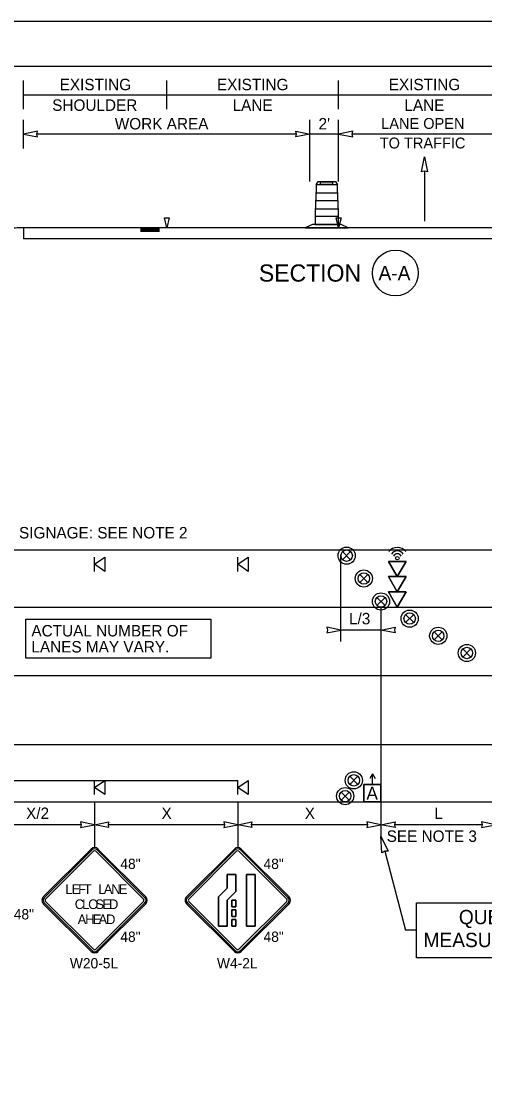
# Model space of a CAD drawing. Extents: x 99999 to 100116, y 99995 to 100013.
# Drawn here: x 100024.26 to 100027.5, y 100003.19 to 100010.69 of the extents above; entities that cross this region are included whole.
import ezdxf

# ---------------------------------------------------------------- set-up
doc = ezdxf.new("R2010")
doc.units = 0
for name, color, linetype in [('RD_ED_ShoulderPavedEdge', 7, 'Continuous'), ('RD_MK_LineEdgeWhite', 7, 'Continuous'), ('RD_MK_LineEdgeYellow', 7, 'Continuous'), ('RD_MK_LineLane', 7, 'Continuous'), ('SH_GI_PlotLimits', 7, 'Continuous'), ('SH_GI_SheetBorder', 7, 'Continuous'), ('SH_TI_Tables', 7, 'Continuous'), ('SH_TI_WZSectionCut', 7, 'Continuous'), ('TR_SN_ConstructionSigns', 7, 'Continuous'), ('TR_WZ_ArrowLeftStrRightTurn', 7, 'Continuous'), ('TR_WZ_PortableSignMountBlk-Org', 7, 'Continuous'), ('TR_WZ_SequentialArrowSign', 7, 'Continuous'), ('TR_WZ_TrafficSafetyDrum', 7, 'Continuous'), ('TR_WZ_TrafficSafetyDrumElev', 7, 'Continuous'), ('TR_WZ_WorkZoneDetails', 7, 'Continuous'), ('TR_WZ_WorkZoneTextCurrent', 7, 'Continuous')]:
    doc.layers.add(name, color=color, linetype=linetype)

msp = doc.modelspace()

# ---------------------------------------------------------------- linework, layer by layer
at = {"layer": 'RD_ED_ShoulderPavedEdge'}
for p, q in [((100021.7753, 100006.9957), (100035.62, 100006.9957)), ((100021.7753, 100005.2357), (100035.62, 100005.2357))]:
    msp.add_line(p, q, dxfattribs=at)
at = {"layer": 'RD_MK_LineEdgeWhite'}
msp.add_line((100021.7753, 100005.6357), (100035.62, 100005.6357), dxfattribs=at)
at = {"layer": 'RD_MK_LineEdgeYellow'}
msp.add_line((100021.7753, 100006.5957), (100035.62, 100006.5957), dxfattribs=at)
at = {"layer": 'RD_MK_LineLane'}
msp.add_lwpolyline([(100035.62, 100006.1157), (100021.7753, 100006.1157)], dxfattribs=at)
at = {"layer": 'SH_GI_PlotLimits'}
msp.add_lwpolyline([(100019.0625, 99999.6875), (100036.0625, 99999.6875), (100036.0625, 100010.6875), (100019.0625, 100010.6875)], close=True, dxfattribs=at)
at = {"layer": 'SH_GI_SheetBorder'}
msp.add_line((100020, 100010.375), (100035.75, 100010.375), dxfattribs=at)
at = {"layer": 'SH_TI_Tables'}
msp.add_lwpolyline([(100024.2941, 100006.511), (100025.5872, 100006.511), (100025.5872, 100006.239), (100024.2941, 100006.239)], close=True, dxfattribs=at)
at = {"layer": 'SH_TI_WZSectionCut'}
for p, q in [((100024.2794, 100010.075), (100024.2794, 100010.275)), ((100025.2794, 100010.075), (100025.2794, 100010.275)), ((100026.4794, 100010.075), (100026.4794, 100010.275)), ((100024.2794, 100010.175), (100025.2794, 100010.175)), ((100025.2794, 100010.175), (100026.4794, 100010.175)), ((100026.4794, 100010.175), (100027.6794, 100010.175)), ((100024.2794, 100009.801), (100024.2794, 100010.001)), ((100026.2794, 100009.57), (100026.2794, 100010.001)), ((100026.4794, 100009.57), (100026.4794, 100010.001)), ((100026.1857, 100009.901), (100024.3731, 100009.901)), ((100026.4794, 100009.901), (100026.2794, 100009.901)), ((100027.5857, 100009.901), (100026.5731, 100009.901)), ((100024.2794, 100009.2449), (100024.2794, 100009.1699)), ((100028.6794, 100009.2449), (100024.2794, 100009.2449)), ((100025.0964, 100009.2397), (100025.2294, 100009.2397)), ((100025.0964, 100009.2341), (100025.2294, 100009.2341)), ((100025.0964, 100009.2284), (100025.2294, 100009.2284)), ((100025.0964, 100009.2232), (100025.2294, 100009.2232)), ((100028.6794, 100009.1699), (100024.2794, 100009.1699))]:
    msp.add_line(p, q, dxfattribs=at)
for points in [[(100024.2794, 100009.901), (100024.3777, 100009.8817), (100024.3731, 100009.901), (100024.3777, 100009.9203)], [(100026.2794, 100009.901), (100026.1811, 100009.8817), (100026.1857, 100009.901), (100026.1811, 100009.9203)], [(100026.4794, 100009.901), (100026.5777, 100009.8817), (100026.5731, 100009.901), (100026.5777, 100009.9203)], [(100025.2627, 100009.3147), (100025.296, 100009.3147), (100025.2794, 100009.2449)], [(100026.4627, 100009.3147), (100026.4961, 100009.3147), (100026.4794, 100009.2449)]]:
    msp.add_lwpolyline(points, close=True, dxfattribs=at)
msp.add_circle((100026.8759, 100008.93), 0.16, dxfattribs=at)
msp.add_open_spline([(100024.2794, 100009.2449), (100024.0282, 100009.2449), (100023.9027, 100009.1828), (100023.7773, 100009.1828)], degree=2, dxfattribs=at)
at = {"layer": 'TR_SN_ConstructionSigns'}
for p, q in [((100024.7514, 100004.9058), (100024.4173, 100004.5717)), ((100024.7574, 100004.8999), (100024.4233, 100004.5658)), ((100024.4332, 100004.5558), (100024.7673, 100004.8899)), ((100024.7832, 100004.8899), (100025.1173, 100004.5558)), ((100025.1273, 100004.5658), (100024.7932, 100004.8999)), ((100025.1333, 100004.5717), (100024.7991, 100004.9058)), ((100025.7514, 100004.9058), (100025.4173, 100004.5717)), ((100025.7574, 100004.8999), (100025.4233, 100004.5658)), ((100025.4332, 100004.5558), (100025.7673, 100004.8899)), ((100025.7832, 100004.8899), (100026.1173, 100004.5558)), ((100026.1273, 100004.5658), (100025.7932, 100004.8999)), ((100026.1333, 100004.5717), (100025.7991, 100004.9058)), ((100025.7612, 100004.7279), (100025.7007, 100004.7279)), ((100025.7007, 100004.7279), (100025.7007, 100004.6334)), ((100025.7007, 100004.6334), (100025.7007, 100004.7279)), ((100025.7007, 100004.7279), (100025.7612, 100004.7279)), ((100025.7612, 100004.6083), (100025.7612, 100004.7279)), ((100025.7612, 100004.7279), (100025.7612, 100004.6083)), ((100025.8969, 100004.7279), (100025.8365, 100004.7279)), ((100025.8365, 100004.7279), (100025.8365, 100004.3679)), ((100025.8365, 100004.3679), (100025.8365, 100004.7279)), ((100025.8365, 100004.7279), (100025.8969, 100004.7279)), ((100025.8969, 100004.3679), (100025.8969, 100004.7279)), ((100025.8969, 100004.7279), (100025.8969, 100004.3679)), ((100025.7007, 100004.6334), (100025.6403, 100004.5729)), ((100025.6403, 100004.5729), (100025.7007, 100004.6334)), ((100025.6403, 100004.5729), (100025.6403, 100004.3679)), ((100025.6403, 100004.3679), (100025.6403, 100004.5729)), ((100025.7007, 100004.5479), (100025.7612, 100004.6083)), ((100025.7612, 100004.6083), (100025.7007, 100004.5479)), ((100024.4173, 100004.524), (100024.7514, 100004.1899)), ((100024.4233, 100004.53), (100024.7574, 100004.1959)), ((100024.7673, 100004.2058), (100024.4332, 100004.5399)), ((100025.1173, 100004.5399), (100024.7832, 100004.2058)), ((100024.7932, 100004.1959), (100025.1273, 100004.53)), ((100024.7991, 100004.1899), (100025.1333, 100004.524)), ((100025.4173, 100004.524), (100025.7514, 100004.1899)), ((100025.4233, 100004.53), (100025.7574, 100004.1959)), ((100025.7673, 100004.2058), (100025.4332, 100004.5399)), ((100025.7007, 100004.3679), (100025.7007, 100004.5479)), ((100025.7007, 100004.5479), (100025.7007, 100004.3679)), ((100025.7612, 100004.5479), (100025.7345, 100004.5479)), ((100025.7345, 100004.5479), (100025.7345, 100004.5029)), ((100025.7345, 100004.5029), (100025.7345, 100004.5479)), ((100025.7345, 100004.5479), (100025.7612, 100004.5479)), ((100025.7345, 100004.5029), (100025.7612, 100004.5029)), ((100025.7612, 100004.5029), (100025.7345, 100004.5029)), ((100025.7612, 100004.5029), (100025.7612, 100004.5479)), ((100025.7612, 100004.5479), (100025.7612, 100004.5029)), ((100026.1173, 100004.5399), (100025.7832, 100004.2058)), ((100025.7932, 100004.1959), (100026.1273, 100004.53)), ((100025.7991, 100004.1899), (100026.1333, 100004.524)), ((100025.7612, 100004.4804), (100025.7345, 100004.4804)), ((100025.7345, 100004.4804), (100025.7345, 100004.4354)), ((100025.7345, 100004.4354), (100025.7345, 100004.4804)), ((100025.7345, 100004.4804), (100025.7612, 100004.4804)), ((100025.7345, 100004.4354), (100025.7612, 100004.4354)), ((100025.7612, 100004.4354), (100025.7345, 100004.4354)), ((100025.7612, 100004.4129), (100025.7345, 100004.4129)), ((100025.7345, 100004.4129), (100025.7345, 100004.3679)), ((100025.7345, 100004.3679), (100025.7345, 100004.4129)), ((100025.7345, 100004.4129), (100025.7612, 100004.4129)), ((100025.7612, 100004.4354), (100025.7612, 100004.4804)), ((100025.7612, 100004.4804), (100025.7612, 100004.4354)), ((100025.7612, 100004.3679), (100025.7612, 100004.4129)), ((100025.7612, 100004.4129), (100025.7612, 100004.3679)), ((100025.6403, 100004.3679), (100025.7007, 100004.3679)), ((100025.7007, 100004.3679), (100025.6403, 100004.3679)), ((100025.7345, 100004.3679), (100025.7612, 100004.3679)), ((100025.7612, 100004.3679), (100025.7345, 100004.3679)), ((100025.8365, 100004.3679), (100025.8969, 100004.3679)), ((100025.8969, 100004.3679), (100025.8365, 100004.3679))]:
    msp.add_line(p, q, dxfattribs=at)
for centre, radius, start, end in [((100024.7753, 100004.882), 0.0338, 45, 135), ((100024.7753, 100004.882), 0.0253, 45, 135), ((100024.7753, 100004.882), 0.0113, 45, 135), ((100025.7753, 100004.882), 0.0338, 45, 135), ((100025.7753, 100004.882), 0.0253, 45, 135), ((100025.7753, 100004.882), 0.0113, 45, 135), ((100024.4412, 100004.5479), 0.0338, 135, 225.00001), ((100024.4412, 100004.5479), 0.0253, 135, 225.00001), ((100025.1094, 100004.5479), 0.0253, 315.00002, 45), ((100025.1094, 100004.5479), 0.0338, 315.00001, 45.00001), ((100025.4412, 100004.5479), 0.0338, 135, 225.00001), ((100025.4412, 100004.5479), 0.0253, 135, 225.00001), ((100026.1094, 100004.5479), 0.0253, 315.00002, 45), ((100026.1094, 100004.5479), 0.0338, 315.00001, 45.00001), ((100024.4412, 100004.5479), 0.0113, 135, 225.00001), ((100025.1094, 100004.5479), 0.0113, 315.00002, 45), ((100025.4412, 100004.5479), 0.0113, 135, 225.00001), ((100026.1094, 100004.5479), 0.0113, 315.00002, 45), ((100024.7753, 100004.2138), 0.0338, 225.00001, 315.00001), ((100024.7753, 100004.2138), 0.0253, 225.00001, 315.00002), ((100024.7753, 100004.2138), 0.0113, 225.00001, 315.00002), ((100025.7753, 100004.2138), 0.0338, 225.00001, 315.00001), ((100025.7753, 100004.2138), 0.0253, 225.00001, 315.00002), ((100025.7753, 100004.2138), 0.0113, 225.00001, 315.00002)]:
    msp.add_arc(centre, radius, start, end, dxfattribs=at)
at = {"layer": 'TR_WZ_ArrowLeftStrRightTurn'}
msp.add_line((100027.0794, 100009.6418), (100027.0794, 100009.292), dxfattribs=at)
msp.add_lwpolyline([(100027.0794, 100009.742), (100027.1, 100009.6369), (100027.0794, 100009.6418), (100027.0588, 100009.6369)], close=True, dxfattribs=at)
at = {"layer": 'TR_WZ_PortableSignMountBlk-Org'}
for p, q in [((100024.7753, 100006.8458), (100024.7753, 100006.9458)), ((100025.7753, 100006.8458), (100025.7753, 100006.9458)), ((100024.7753, 100005.2858), (100024.7753, 100005.3858)), ((100025.7753, 100005.2858), (100025.7753, 100005.3858))]:
    msp.add_line(p, q, dxfattribs=at)
for points in [[(100024.7753, 100006.8957), (100024.8471, 100006.9458), (100024.8471, 100006.8458)], [(100025.7753, 100006.8957), (100025.8471, 100006.9458), (100025.8471, 100006.8458)], [(100024.7753, 100005.3357), (100024.8471, 100005.3858), (100024.8471, 100005.2858)], [(100025.7753, 100005.3357), (100025.8471, 100005.3858), (100025.8471, 100005.2858)]]:
    msp.add_lwpolyline(points, close=True, dxfattribs=at)
at = {"layer": 'TR_WZ_SequentialArrowSign'}
for points in [[(100026.8895, 100006.8091), (100026.8278, 100006.9157), (100026.9513, 100006.9157), (100026.8895, 100006.8091)], [(100026.9513, 100006.9157), (100026.8278, 100006.9157), (100026.8895, 100006.8091), (100026.9513, 100006.9157)], [(100026.8895, 100006.7024), (100026.8278, 100006.8091), (100026.8895, 100006.8091), (100026.9513, 100006.8091), (100026.8895, 100006.7024)], [(100026.9513, 100006.8091), (100026.8895, 100006.8091), (100026.8278, 100006.8091), (100026.8895, 100006.7024), (100026.9513, 100006.8091)], [(100026.8895, 100006.5957), (100026.8278, 100006.7024), (100026.8895, 100006.7024), (100026.9513, 100006.7024), (100026.8895, 100006.5957)], [(100026.9513, 100006.7024), (100026.8895, 100006.7024), (100026.8278, 100006.7024), (100026.8895, 100006.5957), (100026.9513, 100006.7024)]]:
    msp.add_lwpolyline(points, dxfattribs=at)
msp.add_circle((100026.8895, 100006.9382), 0.0125, dxfattribs=at)
for radius, start, end in [(0.075, 37.32912, 142.67088), (0.05, 33.97816, 146.02184), (0.03, 27.15796, 152.84204)]:
    msp.add_arc((100026.8895, 100006.9382), radius, start, end, dxfattribs=at)
at = {"layer": 'TR_WZ_TrafficSafetyDrum'}
for p, q in [((100026.507, 100006.9274), (100026.5636, 100006.984)), ((100026.5636, 100006.9274), (100026.507, 100006.984)), ((100026.627, 100006.7674), (100026.6836, 100006.824)), ((100026.6836, 100006.7674), (100026.627, 100006.824)), ((100026.747, 100006.6074), (100026.8036, 100006.664)), ((100026.8036, 100006.6074), (100026.747, 100006.664)), ((100026.947, 100006.4874), (100027.0036, 100006.544)), ((100027.0036, 100006.4874), (100026.947, 100006.544)), ((100027.147, 100006.3674), (100027.2036, 100006.424)), ((100027.2036, 100006.3674), (100027.147, 100006.424)), ((100027.347, 100006.2474), (100027.4036, 100006.304)), ((100027.4036, 100006.2474), (100027.347, 100006.304)), ((100026.557, 100005.414), (100026.6136, 100005.3574)), ((100026.6136, 100005.414), (100026.557, 100005.3574)), ((100026.497, 100005.304), (100026.5536, 100005.2474)), ((100026.5536, 100005.304), (100026.497, 100005.2474))]:
    msp.add_line(p, q, dxfattribs=at)
for centre, radius in [((100026.5353, 100006.9557), 0.06), ((100026.5353, 100006.9557), 0.06), ((100026.5353, 100006.9557), 0.04), ((100026.6553, 100006.7957), 0.06), ((100026.6553, 100006.7957), 0.06), ((100026.6553, 100006.7957), 0.04), ((100026.7753, 100006.6357), 0.06), ((100026.7753, 100006.6357), 0.06), ((100026.7753, 100006.6357), 0.04), ((100026.9753, 100006.5157), 0.06), ((100026.9753, 100006.5157), 0.06), ((100026.9753, 100006.5157), 0.04), ((100027.1753, 100006.3957), 0.06), ((100027.1753, 100006.3957), 0.06), ((100027.1753, 100006.3957), 0.04), ((100027.3753, 100006.2757), 0.06), ((100027.3753, 100006.2757), 0.06), ((100027.3753, 100006.2757), 0.04), ((100026.5853, 100005.3857), 0.06), ((100026.5853, 100005.3857), 0.06), ((100026.5853, 100005.3857), 0.04), ((100026.5253, 100005.2757), 0.06), ((100026.5253, 100005.2757), 0.06), ((100026.5253, 100005.2757), 0.04)]:
    msp.add_circle(centre, radius, dxfattribs=at)
at = {"layer": 'TR_WZ_TrafficSafetyDrumElev'}
for p, q in [((100026.471, 100009.545), (100026.323, 100009.545)), ((100026.471, 100009.545), (100026.323, 100009.545)), ((100026.4365, 100009.564), (100026.3547, 100009.564)), ((100026.3547, 100009.551), (100026.4365, 100009.551)), ((100026.4738, 100009.4871), (100026.3202, 100009.4871)), ((100026.3202, 100009.4871), (100026.3202, 100009.4372)), ((100026.3202, 100009.4372), (100026.4738, 100009.4372)), ((100026.4738, 100009.4372), (100026.4738, 100009.4871)), ((100026.4775, 100009.377), (100026.3165, 100009.377)), ((100026.3165, 100009.377), (100026.3165, 100009.3271)), ((100026.4775, 100009.3271), (100026.4775, 100009.377)), ((100026.3165, 100009.3271), (100026.4775, 100009.3271))]:
    msp.add_line(p, q, dxfattribs=at)
for points in [[(100026.322, 100009.543), (100026.322, 100009.4915)], [(100026.322, 100009.543), (100026.322, 100009.4915)], [(100026.472, 100009.4915), (100026.472, 100009.543)], [(100026.472, 100009.4915), (100026.472, 100009.543)], [(100026.3183, 100009.4327), (100026.3183, 100009.3814)], [(100026.3183, 100009.4327), (100026.3183, 100009.3814)], [(100026.3202, 100009.4878), (100026.3202, 100009.4365)], [(100026.3202, 100009.4878), (100026.3202, 100009.4365)], [(100026.4738, 100009.4365), (100026.4738, 100009.4878)], [(100026.4738, 100009.4365), (100026.4738, 100009.4878)], [(100026.4757, 100009.3814), (100026.4757, 100009.4327)], [(100026.4757, 100009.3814), (100026.4757, 100009.4327)], [(100026.3165, 100009.3777), (100026.3165, 100009.3264)], [(100026.3165, 100009.3777), (100026.3165, 100009.3264)], [(100026.4775, 100009.3264), (100026.4775, 100009.3777)], [(100026.4775, 100009.3264), (100026.4775, 100009.3777)], [(100026.3146, 100009.3226), (100026.3146, 100009.27), (100026.4794, 100009.27), (100026.4794, 100009.3226)], [(100026.3146, 100009.3226), (100026.3146, 100009.27), (100026.4794, 100009.27), (100026.4794, 100009.3226)]]:
    msp.add_lwpolyline(points, dxfattribs=at)
for points in [[(100026.323, 100009.545), (100026.3361, 100009.57), (100026.4579, 100009.57), (100026.471, 100009.545)], [(100026.547, 100009.245), (100026.4968, 100009.27), (100026.2972, 100009.27), (100026.247, 100009.245)]]:
    msp.add_lwpolyline(points, close=True, dxfattribs=at)
for centre, major_axis, ratio, start_param, end_param in [((100026.3232, 100009.5426), (0, 0.00249), 0.493438, 0.177149, 1.393647), ((100026.3232, 100009.5426), (0, 0.00249), 0.493438, 0.177149, 1.393647), ((100026.3547, 100009.5575), (0, 0.0065), 0.570305, 6.283185, 9.424778), ((100026.4365, 100009.5575), (0, 0.0065), 0.570305, 3.141593, 6.283185), ((100026.4708, 100009.5426), (0, 0.00249), 0.493438, 4.889538, 6.106036), ((100026.4708, 100009.5426), (0, 0.00249), 0.493438, 4.889538, 6.106036), ((100026.3217, 100009.4296), (0, 0.00758), 0.493438, 0.4288, 1.141997), ((100026.3217, 100009.4296), (0, 0.00758), 0.493438, 0.4288, 1.141997), ((100026.3236, 100009.4846), (0, 0.00758), 0.493438, 0.4288, 1.141997), ((100026.3236, 100009.4846), (0, 0.00758), 0.493438, 0.4288, 1.141997), ((100026.4704, 100009.4846), (0, 0.00758), 0.493438, 5.141189, 5.854386), ((100026.4704, 100009.4846), (0, 0.00758), 0.493438, 5.141189, 5.854386), ((100026.4723, 100009.4296), (0, 0.00758), 0.493438, 5.141189, 5.854386), ((100026.4723, 100009.4296), (0, 0.00758), 0.493438, 5.141189, 5.854386), ((100026.3199, 100009.3745), (0, 0.00758), 0.493438, 0.4288, 1.141997), ((100026.3199, 100009.3745), (0, 0.00758), 0.493438, 0.4288, 1.141997), ((100026.4741, 100009.3745), (0, 0.00758), 0.493438, 5.141189, 5.854386), ((100026.4741, 100009.3745), (0, 0.00758), 0.493438, 5.141189, 5.854386), ((100026.318, 100009.3195), (0, 0.00758), 0.493438, 0.4288, 1.141997), ((100026.318, 100009.3195), (0, 0.00758), 0.493438, 0.4288, 1.141997), ((100026.476, 100009.3195), (0, 0.00758), 0.493438, 5.141189, 5.854386), ((100026.476, 100009.3195), (0, 0.00758), 0.493438, 5.141189, 5.854386)]:
    msp.add_ellipse(centre, major_axis=major_axis, ratio=ratio, start_param=start_param, end_param=end_param, dxfattribs=at)
at = {"layer": 'TR_WZ_WorkZoneDetails'}
for p, q in [((100026.4953, 100006.3557), (100026.4953, 100006.9557)), ((100026.7753, 100006.5957), (100026.7753, 100004.9957)), ((100026.7753, 100006.4357), (100026.4953, 100006.4357)), ((100023.1753, 100005.3858), (100025.7753, 100005.3858)), ((100026.7153, 100005.4307), (100026.6965, 100005.3983)), ((100026.7153, 100005.3557), (100026.7153, 100005.4307)), ((100026.7153, 100005.4307), (100026.734, 100005.3983)), ((100024.7753, 100005.236), (100024.7753, 100004.9157)), ((100025.7753, 100005.236), (100025.7753, 100004.9157)), ((100024.6815, 100005.0757), (100024.069, 100005.0757)), ((100025.6815, 100005.0757), (100024.869, 100005.0757)), ((100026.6815, 100005.0757), (100025.869, 100005.0757)), ((100027.4815, 100005.0757), (100026.869, 100005.0757))]:
    msp.add_line(p, q, dxfattribs=at)
for points in [[(100026.4953, 100006.4357), (100026.397, 100006.455), (100026.4016, 100006.4357), (100026.397, 100006.4165)], [(100026.7753, 100006.4357), (100026.8736, 100006.455), (100026.869, 100006.4357), (100026.8736, 100006.4165)], [(100026.6553, 100005.3557), (100026.7753, 100005.3557), (100026.7753, 100005.2357), (100026.6553, 100005.2357)], [(100024.7753, 100005.0757), (100024.677, 100005.095), (100024.6815, 100005.0757), (100024.677, 100005.0565)], [(100024.7753, 100005.0757), (100024.8736, 100005.095), (100024.869, 100005.0757), (100024.8736, 100005.0565)], [(100025.7753, 100005.0757), (100025.677, 100005.095), (100025.6815, 100005.0757), (100025.677, 100005.0565)], [(100025.7753, 100005.0757), (100025.8736, 100005.095), (100025.869, 100005.0757), (100025.8736, 100005.0565)], [(100026.7753, 100005.0757), (100026.677, 100005.095), (100026.6815, 100005.0757), (100026.677, 100005.0565)], [(100026.7753, 100005.0757), (100026.8736, 100005.095), (100026.869, 100005.0757), (100026.8736, 100005.0565)], [(100027.5753, 100005.0757), (100027.477, 100005.095), (100027.4815, 100005.0757), (100027.477, 100005.0565)]]:
    msp.add_lwpolyline(points, close=True, dxfattribs=at)
msp.add_lwpolyline([(100026.6553, 100005.3557), (100026.6553, 100005.2357), (100026.7753, 100005.2357), (100026.7753, 100005.3557), (100026.7153, 100005.3557), (100026.6553, 100005.3557)], dxfattribs=at)
at = {"layer": 'TR_WZ_WorkZoneTextCurrent'}
for p in [(100026.8026, 100004.8906), (100027.0222, 100004.338)]:
    msp.add_line(p, (100026.946, 100004.338), dxfattribs=at)
for points in [[(100026.7753, 100004.9957), (100026.8254, 100004.8911), (100026.8025, 100004.8906), (100026.7822, 100004.8799)], [(100027.0222, 100004.5305), (100028.8727, 100004.5305), (100028.8727, 100004.1455), (100027.0222, 100004.1455)]]:
    msp.add_lwpolyline(points, close=True, dxfattribs=at)

# ---------------------------------------------------------------- texts
at = {"layer": 'SH_TI_Tables'}
for s, p in [('ACTUAL NUMBER OF', (100024.3341, 100006.391)), ('LANES MAY VARY.', (100024.3341, 100006.279))]:
    msp.add_text(s, height=0.08, rotation=360, dxfattribs=at).set_placement(p)
at = {"layer": 'SH_TI_WZSectionCut'}
for s, height, p in [('EXISTING', 0.08, (100024.5311, 100010.207)), ('EXISTING', 0.08, (100025.6296, 100010.207)), ('EXISTING', 0.08, (100026.8296, 100010.207)), ('SHOULDER', 0.08, (100024.4792, 100010.063)), ('LANE', 0.08, (100025.739, 100010.063)), ('LANE', 0.08, (100026.939, 100010.063)), ('SECTION', 0.12, (100025.9229, 100008.87)), ('A-A', 0.1, (100026.7581, 100008.88))]:
    msp.add_text(s, height=height, rotation=360, dxfattribs=at).set_placement(p)
for s, height, p in [('WORK AREA', 0.08, (100024.9165, 100009.933)), ("2'", 0.08, (100026.3394, 100009.933)), ('LANE OPEN', 0.076, (100026.7768, 100009.937)), ('TO TRAFFIC', 0.076, (100026.7667, 100009.8002))]:
    msp.add_text(s, height=height, dxfattribs=at).set_placement(p)
at = {"layer": 'TR_SN_ConstructionSigns'}
for s, p in [('48"', (100024.9551, 100004.7664)), ('48"', (100025.9551, 100004.7664)), ('48"', (100024.211, 100004.414)), ('48"', (100024.9551, 100004.2573)), ('48"', (100025.9551, 100004.2573)), ('W20-5L', (100024.6027, 100004.072)), ('W4-2L', (100025.6299, 100004.072))]:
    msp.add_text(s, height=0.072, rotation=360, dxfattribs=at).set_placement(p)
for s, p in [('L', (100024.5711, 100004.5922)), ('E', (100024.615, 100004.5922)), ('F', (100024.6609, 100004.5922)), ('T', (100024.6993, 100004.5922)), ('L', (100024.8013, 100004.5922)), ('A', (100024.8397, 100004.5922)), ('N', (100024.8924, 100004.5922)), ('E', (100024.945, 100004.5922)), ('C', (100024.6369, 100004.4867)), ('L', (100024.6882, 100004.4867)), ('O', (100024.7307, 100004.4867)), ('S', (100024.7807, 100004.4867)), ('E', (100024.83, 100004.4867)), ('D', (100024.8759, 100004.4867)), ('A', (100024.6572, 100004.3812)), ('H', (100024.7098, 100004.3812)), ('E', (100024.7625, 100004.3812)), ('A', (100024.803, 100004.3812)), ('D', (100024.8556, 100004.3812))]:
    msp.add_text(s, height=0.0675, dxfattribs=at).set_placement(p)
at = {"layer": 'TR_WZ_WorkZoneDetails'}
msp.add_text('A', height=0.09, dxfattribs=at).set_placement((100026.6737, 100005.2507))
at = {"layer": 'TR_WZ_WorkZoneTextCurrent'}
for s, height, p in [('LEFT SHOULDER SIGNAGE: SEE NOTE 2', 0.08, (100023.3319, 100007.0757)), ('L/3', 0.08, (100026.5521, 100006.4757)), ('QUEUE LOCATION', 0.1, (100027.3191, 100004.3805)), ('MEASURED FROM HERE', 0.1, (100027.0722, 100004.2205))]:
    msp.add_text(s, height=height, dxfattribs=at).set_placement(p)
for s, p in [('X/2', (100024.2968, 100005.1157)), ('X', (100025.2428, 100005.1157)), ('X', (100026.2428, 100005.1157)), ('L', (100027.1481, 100005.1157)), ('SEE NOTE 3', (100026.8151, 100004.9557))]:
    msp.add_text(s, height=0.08, rotation=360, dxfattribs=at).set_placement(p)

doc.saveas('drawing.dxf')
